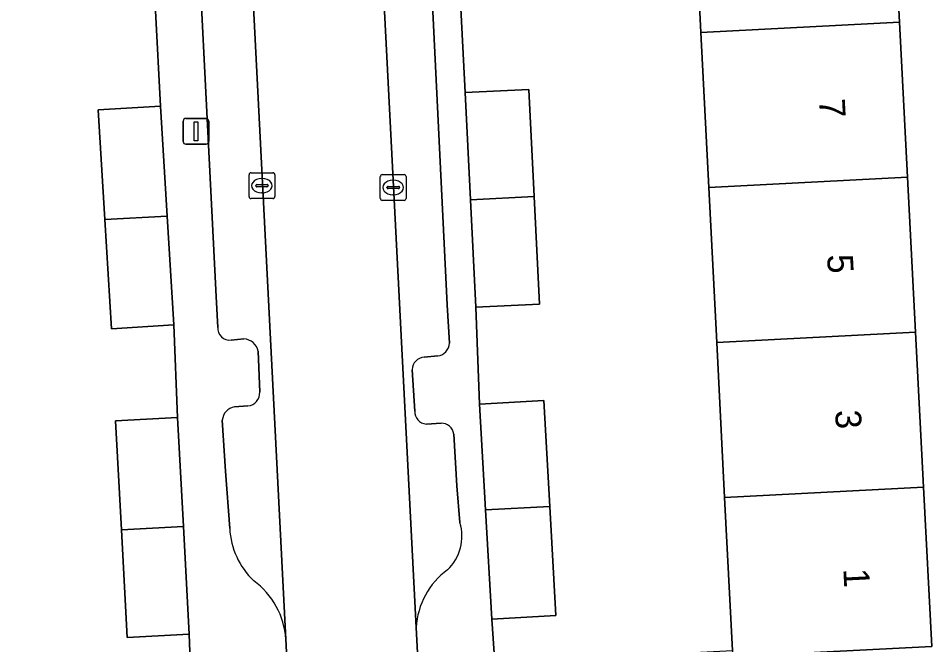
# Model space of a CAD drawing. Extents: x 161084 to 161928, y 385354 to 386522.
# Drawn here: x 161389.16 to 161424.42, y 385459.74 to 385484.1 of the extents above; entities that cross this region are included whole.
import ezdxf

# ---------------------------------------------------------------- set-up
doc = ezdxf.new("R2010")
doc.units = 0
for name, color, linetype in [('IMGEO_Erf', 7, 'Continuous'), ('IMGEO_Kolk', 7, 'Continuous'), ('IMGEO_Lichtmast', 7, 'Continuous'), ('IMGEO_Pand', 7, 'Continuous'), ('IMGEO_Pand_nummerreeks', 7, 'Continuous'), ('IMGEO_Parkeervlak_open', 7, 'Continuous'), ('IMGEO_Rijbaan_lokaal_open', 7, 'Continuous'), ('IMGEO_Voetpad_open', 7, 'Continuous')]:
    doc.layers.add(name, color=color, linetype=linetype)

msp = doc.modelspace()

# ---------------------------------------------------------------- linework, layer by layer
at = {"layer": 'IMGEO_Erf'}
for points in [[(161425.182, 385526.476), (161421.216, 385526.254), (161421.535, 385520.062), (161421.846, 385514.041), (161422.156, 385508.02), (161422.467, 385501.999), (161422.57, 385500), (161422.777, 385495.978), (161423.088, 385489.958), (161423.399, 385483.937), (161423.709, 385477.916), (161424.02, 385471.895), (161424.33, 385465.874), (161424.65, 385459.679), (161419.05, 385459.388), (161419.359, 385453.441), (161419.358, 385452.841), (161429.459, 385453.441)], [(161406.331, 385484.996), (161406.529, 385481.207), (161408.997, 385481.329), (161409.204, 385477.166), (161409.411, 385472.989), (161406.943, 385472.867), (161407.079, 385469.098), (161409.574, 385469.24), (161409.808, 385465.124), (161410.049, 385460.885), (161407.554, 385460.743), (161407.671, 385459.044), (161409.7, 385459.15), (161412.813, 385459.311), (161415.925, 385459.473), (161416.902, 385459.524), (161416.6, 385465.475), (161416.294, 385471.496), (161415.989, 385477.517), (161415.683, 385483.538), (161415.378, 385489.56)], [(161388.381, 385458.064), (161391.476, 385458.224), (161394.572, 385458.384), (161395.872, 385458.451), (161395.808, 385460.155), (161393.401, 385460.025), (161393.175, 385464.215), (161392.946, 385468.444), (161395.353, 385468.574), (161395.205, 385472.174), (161392.788, 385472.027), (161392.529, 385476.271), (161392.27, 385480.529), (161394.687, 385480.676), (161394.502, 385484.379)]]:
    msp.add_lwpolyline(points, dxfattribs=at)
at = {"layer": 'IMGEO_Kolk'}
for p, q in [((161398.13, 385477.162), (161398.13, 385478.014)), ((161398.205, 385478.088), (161399.057, 385478.088)), ((161398.618, 385477.868), (161398.643, 385477.868)), ((161399.131, 385478.014), (161399.131, 385477.162)), ((161403.228, 385477.09), (161403.228, 385477.942)), ((161403.303, 385478.016), (161404.155, 385478.016)), ((161404.229, 385477.942), (161404.229, 385477.09)), ((161398.389, 385477.582), (161398.389, 385477.594)), ((161398.827, 385477.545), (161398.429, 385477.545)), ((161398.432, 385477.631), (161398.83, 385477.631)), ((161398.873, 385477.594), (161398.873, 385477.582)), ((161403.487, 385477.51), (161403.487, 385477.522)), ((161403.925, 385477.473), (161403.527, 385477.473)), ((161403.53, 385477.559), (161403.928, 385477.559)), ((161403.716, 385477.796), (161403.741, 385477.796)), ((161403.971, 385477.522), (161403.971, 385477.51)), ((161398.641, 385477.308), (161398.616, 385477.308)), ((161403.739, 385477.236), (161403.714, 385477.236)), ((161399.057, 385477.088), (161398.205, 385477.088)), ((161404.155, 385477.016), (161403.303, 385477.016))]:
    msp.add_line(p, q, dxfattribs=at)
for points in [[(161398.13, 385477.162), (161398.13, 385478.014)], [(161398.205, 385478.088), (161399.057, 385478.088)], [(161399.131, 385478.014), (161399.131, 385477.162)], [(161403.228, 385477.09), (161403.228, 385477.942)], [(161403.303, 385478.016), (161404.155, 385478.016)], [(161404.229, 385477.942), (161404.229, 385477.09)], [(161399.057, 385477.088), (161398.205, 385477.088)], [(161404.155, 385477.016), (161403.303, 385477.016)]]:
    msp.add_lwpolyline(points, dxfattribs=at)
for centre, radius, start, end in [((161398.207, 385478.012), 0.0765, 91.552, 178.448), ((161398.207, 385478.012), 0.0765, 91.552, 178.448), ((161399.055, 385478.012), 0.0765, 1.552, 88.448), ((161399.055, 385478.012), 0.0765, 1.552, 88.448), ((161403.305, 385477.94), 0.0765, 91.552, 178.448), ((161403.305, 385477.94), 0.0765, 91.552, 178.448), ((161404.153, 385477.94), 0.0765, 1.552, 88.448), ((161404.153, 385477.94), 0.0765, 1.552, 88.448), ((161398.429, 385477.591), 0.0403, 85.8775, 175.7526), ((161398.426, 385477.581), 0.0366, 178.938, 274.7102), ((161398.83, 385477.588), 0.043, 264.8664, 352.4533), ((161398.834, 385477.593), 0.0386, 1.7309, 96.639), ((161403.527, 385477.519), 0.0403, 85.8775, 175.7526), ((161403.524, 385477.509), 0.0366, 178.938, 274.7102), ((161403.928, 385477.516), 0.043, 264.8664, 352.4533), ((161403.932, 385477.521), 0.0386, 1.7309, 96.639), ((161398.207, 385477.164), 0.0765, 181.552, 268.448), ((161398.207, 385477.164), 0.0765, 181.552, 268.448), ((161399.055, 385477.164), 0.0765, 271.552, 358.448), ((161399.055, 385477.164), 0.0765, 271.552, 358.448), ((161403.305, 385477.092), 0.0765, 181.552, 268.448), ((161403.305, 385477.092), 0.0765, 181.552, 268.448), ((161404.153, 385477.092), 0.0765, 271.552, 358.448), ((161404.153, 385477.092), 0.0765, 271.552, 358.448)]:
    msp.add_arc(centre, radius, start, end, dxfattribs=at)
for centre, major_axis, ratio, start_param, end_param in [((161398.617, 385477.588), (-0.387, 0.002), 0.722429, 4.712389, 7.853982), ((161398.642, 385477.588), (-0.39, 0.002), 0.717154, 1.570796, 4.712389), ((161403.715, 385477.516), (-0.387, 0.002), 0.722429, 4.712389, 7.853982), ((161403.74, 385477.516), (-0.39, 0.002), 0.717154, 1.570796, 4.712389)]:
    msp.add_ellipse(centre, major_axis=major_axis, ratio=ratio, start_param=start_param, end_param=end_param, dxfattribs=at)
at = {"layer": 'IMGEO_Lichtmast'}
for p, q in [((161395.571, 385479.3), (161395.571, 385480.1)), ((161395.571, 385480.1), (161395.571, 385479.3)), ((161395.671, 385480.2), (161396.461, 385480.2)), ((161396.461, 385480.2), (161395.671, 385480.2)), ((161396.561, 385480.1), (161396.561, 385479.3)), ((161396.561, 385479.3), (161396.561, 385480.1)), ((161396.461, 385479.2), (161395.671, 385479.2)), ((161395.671, 385479.2), (161396.461, 385479.2))]:
    msp.add_line(p, q, dxfattribs=at)
msp.add_lwpolyline([(161395.991, 385480.075), (161396.141, 385480.075), (161396.141, 385479.325), (161395.991, 385479.325), (161395.991, 385480.075)], dxfattribs=at)
for centre, start, end in [((161395.671, 385480.1), 90, 180), ((161395.671, 385480.1), 90, 180), ((161396.461, 385480.1), 0, 90), ((161396.461, 385480.1), 360, 90), ((161395.671, 385479.3), 180, 270), ((161395.671, 385479.3), 180, 270), ((161396.461, 385479.3), 270, 0), ((161396.461, 385479.3), 270, 0)]:
    msp.add_arc(centre, 0.1, start, end, dxfattribs=at)
at = {"layer": 'IMGEO_Pand'}
for points in [[(161423.399, 385483.937), (161423.088, 385489.958), (161415.378, 385489.56), (161415.683, 385483.538)], [(161415.683, 385483.538), (161415.989, 385477.517), (161423.709, 385477.916), (161423.399, 385483.937)], [(161406.736, 385477.039), (161409.204, 385477.166), (161408.997, 385481.329), (161406.529, 385481.207)], [(161394.687, 385480.676), (161392.27, 385480.529), (161392.529, 385476.271), (161394.948, 385476.397)], [(161424.02, 385471.895), (161423.709, 385477.916), (161415.989, 385477.517), (161416.294, 385471.496)], [(161406.943, 385472.867), (161409.411, 385472.989), (161409.204, 385477.166), (161406.736, 385477.039)], [(161394.948, 385476.397), (161392.529, 385476.271), (161392.788, 385472.027), (161395.205, 385472.174)], [(161416.294, 385471.496), (161416.6, 385465.475), (161424.33, 385465.874), (161424.02, 385471.895)], [(161407.312, 385464.996), (161409.808, 385465.124), (161409.574, 385469.24), (161407.079, 385469.098)], [(161395.353, 385468.574), (161392.946, 385468.444), (161393.175, 385464.215), (161395.582, 385464.341)], [(161416.914, 385459.279), (161419.05, 385459.388), (161424.65, 385459.679), (161424.33, 385465.874), (161416.6, 385465.475), (161416.902, 385459.524)], [(161407.554, 385460.743), (161410.049, 385460.885), (161409.808, 385465.124), (161407.312, 385464.996)], [(161395.582, 385464.341), (161393.175, 385464.215), (161393.401, 385460.025), (161395.808, 385460.155)]]:
    msp.add_lwpolyline(points, close=True, dxfattribs=at)
at = {"layer": 'IMGEO_Parkeervlak_open'}
for points in [[(161401.636, 385518.603), (161402.21, 385505.43), (161402.592, 385500), (161404.623, 385460.419)], [(161399.561, 385459.962), (161397.507, 385500), (161396.523, 385518.161)], [(161405.911, 385471.462), (161405.819, 385472.957), (161404.502, 385500), (161404.307, 385504.135), (161404.172, 385506.471)], [(161395.804, 385494.019), (161395.854, 385493.005), (161396.855, 385473.285), (161396.915, 385472.082)], [(161397.431, 385471.59), (161397.929, 385471.63)], [(161398.479, 385471.151), (161398.545, 385469.567)], [(161404.933, 385470.922), (161405.464, 385470.972)], [(161404.563, 385468.829), (161404.468, 385470.435)], [(161398.082, 385469.029), (161397.568, 385468.993)], [(161397.089, 385468.476), (161397.208, 385466.493), (161397.377, 385464.267)], [(161405.587, 385468.357), (161405.015, 385468.324)], [(161406.317, 385464.497), (161406.199, 385465.922), (161406.083, 385467.936)]]:
    msp.add_lwpolyline(points, dxfattribs=at)
for centre, radius, start, end in [((161397.374, 385472.047), 0.46, 175.6257, 277.1022), ((161397.913, 385471.056), 0.574, 9.4945, 88.3997), ((161405.393, 385471.485), 0.518, 277.8507, 357.4043), ((161404.957, 385470.434), 0.489, 92.8011, 179.8466), ((161398.03, 385469.542), 0.516, 275.8121, 2.7576), ((161397.656, 385468.431), 0.568, 98.8762, 175.4937), ((161405.054, 385468.814), 0.491, 178.2079, 265.4524), ((161405.593, 385467.861), 0.496, 8.6689, 90.6826), ((161404.595, 385463.961), 1.803, 313.6975, 17.2941), ((161400.385, 385464.417), 3.011, 182.8473, 226.4812), ((161407.571, 385460.265), 2.952, 125.8755, 177.0113), ((161396.503, 385459.758), 3.065, 3.812, 53.8464)]:
    msp.add_arc(centre, radius, start, end, dxfattribs=at)
at = {"layer": 'IMGEO_Rijbaan_lokaal_open'}
for points in [[(161404.623, 385460.419), (161402.592, 385500), (161402.21, 385505.43), (161401.636, 385518.603)], [(161396.523, 385518.161), (161397.507, 385500), (161399.561, 385459.962)], [(161405.017, 385452.752), (161404.623, 385460.419)], [(161399.561, 385459.962), (161399.952, 385452.344)]]:
    msp.add_lwpolyline(points, dxfattribs=at)
at = {"layer": 'IMGEO_Voetpad_open'}
for points in [[(161404.172, 385506.471), (161404.307, 385504.135), (161404.502, 385500), (161405.819, 385472.957), (161405.911, 385471.462)], [(161396.915, 385472.082), (161396.855, 385473.285), (161395.854, 385493.005), (161395.804, 385494.019)], [(161404.623, 385460.419), (161405.017, 385452.752), (161406.91, 385452.794), (161406.588, 385458.988), (161407.671, 385459.044), (161407.554, 385460.743), (161407.312, 385464.996), (161407.079, 385469.098), (161406.943, 385472.867), (161406.736, 385477.039), (161406.529, 385481.207), (161406.331, 385484.996)], [(161394.502, 385484.379), (161394.687, 385480.676), (161394.948, 385476.397), (161395.205, 385472.174), (161395.353, 385468.574), (161395.582, 385464.341), (161395.808, 385460.155), (161395.872, 385458.451), (161397.668, 385458.544), (161397.992, 385452.272), (161399.952, 385452.344), (161399.561, 385459.962)], [(161397.929, 385471.63), (161397.431, 385471.59)], [(161398.545, 385469.567), (161398.479, 385471.151)], [(161405.464, 385470.972), (161404.933, 385470.922)], [(161404.468, 385470.435), (161404.563, 385468.829)], [(161397.568, 385468.993), (161398.082, 385469.029)], [(161397.377, 385464.267), (161397.208, 385466.493), (161397.089, 385468.476)], [(161405.015, 385468.324), (161405.587, 385468.357)], [(161406.083, 385467.936), (161406.199, 385465.922), (161406.317, 385464.497)]]:
    msp.add_lwpolyline(points, dxfattribs=at)
for centre, radius, start, end in [((161397.374, 385472.047), 0.46, 175.6257, 277.1022), ((161397.913, 385471.056), 0.574, 9.4945, 88.3997), ((161405.393, 385471.485), 0.518, 277.8507, 357.4043), ((161404.957, 385470.434), 0.489, 92.8011, 179.8466), ((161398.03, 385469.542), 0.516, 275.8121, 2.7576), ((161397.656, 385468.431), 0.568, 98.8762, 175.4937), ((161405.054, 385468.814), 0.491, 178.2079, 265.4524), ((161405.593, 385467.861), 0.496, 8.6689, 90.6826), ((161404.595, 385463.961), 1.803, 313.6975, 17.2941), ((161400.385, 385464.417), 3.011, 182.8473, 226.4812), ((161407.571, 385460.265), 2.952, 125.8755, 177.0113), ((161396.503, 385459.758), 3.065, 3.812, 53.8464)]:
    msp.add_arc(centre, radius, start, end, dxfattribs=at)

# ---------------------------------------------------------------- texts
at = {"layer": 'IMGEO_Pand_nummerreeks'}
for s, p in [('7', (161420.268, 385480.945)), ('5', (161420.58, 385474.899)), ('3', (161420.892, 385468.853)), ('1', (161421.21, 385462.693))]:
    msp.add_text(s, height=1, rotation=272.953, dxfattribs=at).set_placement(p)

doc.saveas('drawing.dxf')
